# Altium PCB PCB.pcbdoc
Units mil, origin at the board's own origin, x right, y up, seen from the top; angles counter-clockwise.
Board outline 1473.55 x 1860 mil, 2 copper layers (Top Layer, Bottom Layer); 3 components, 4 nets, 11 pads, 0 vias.
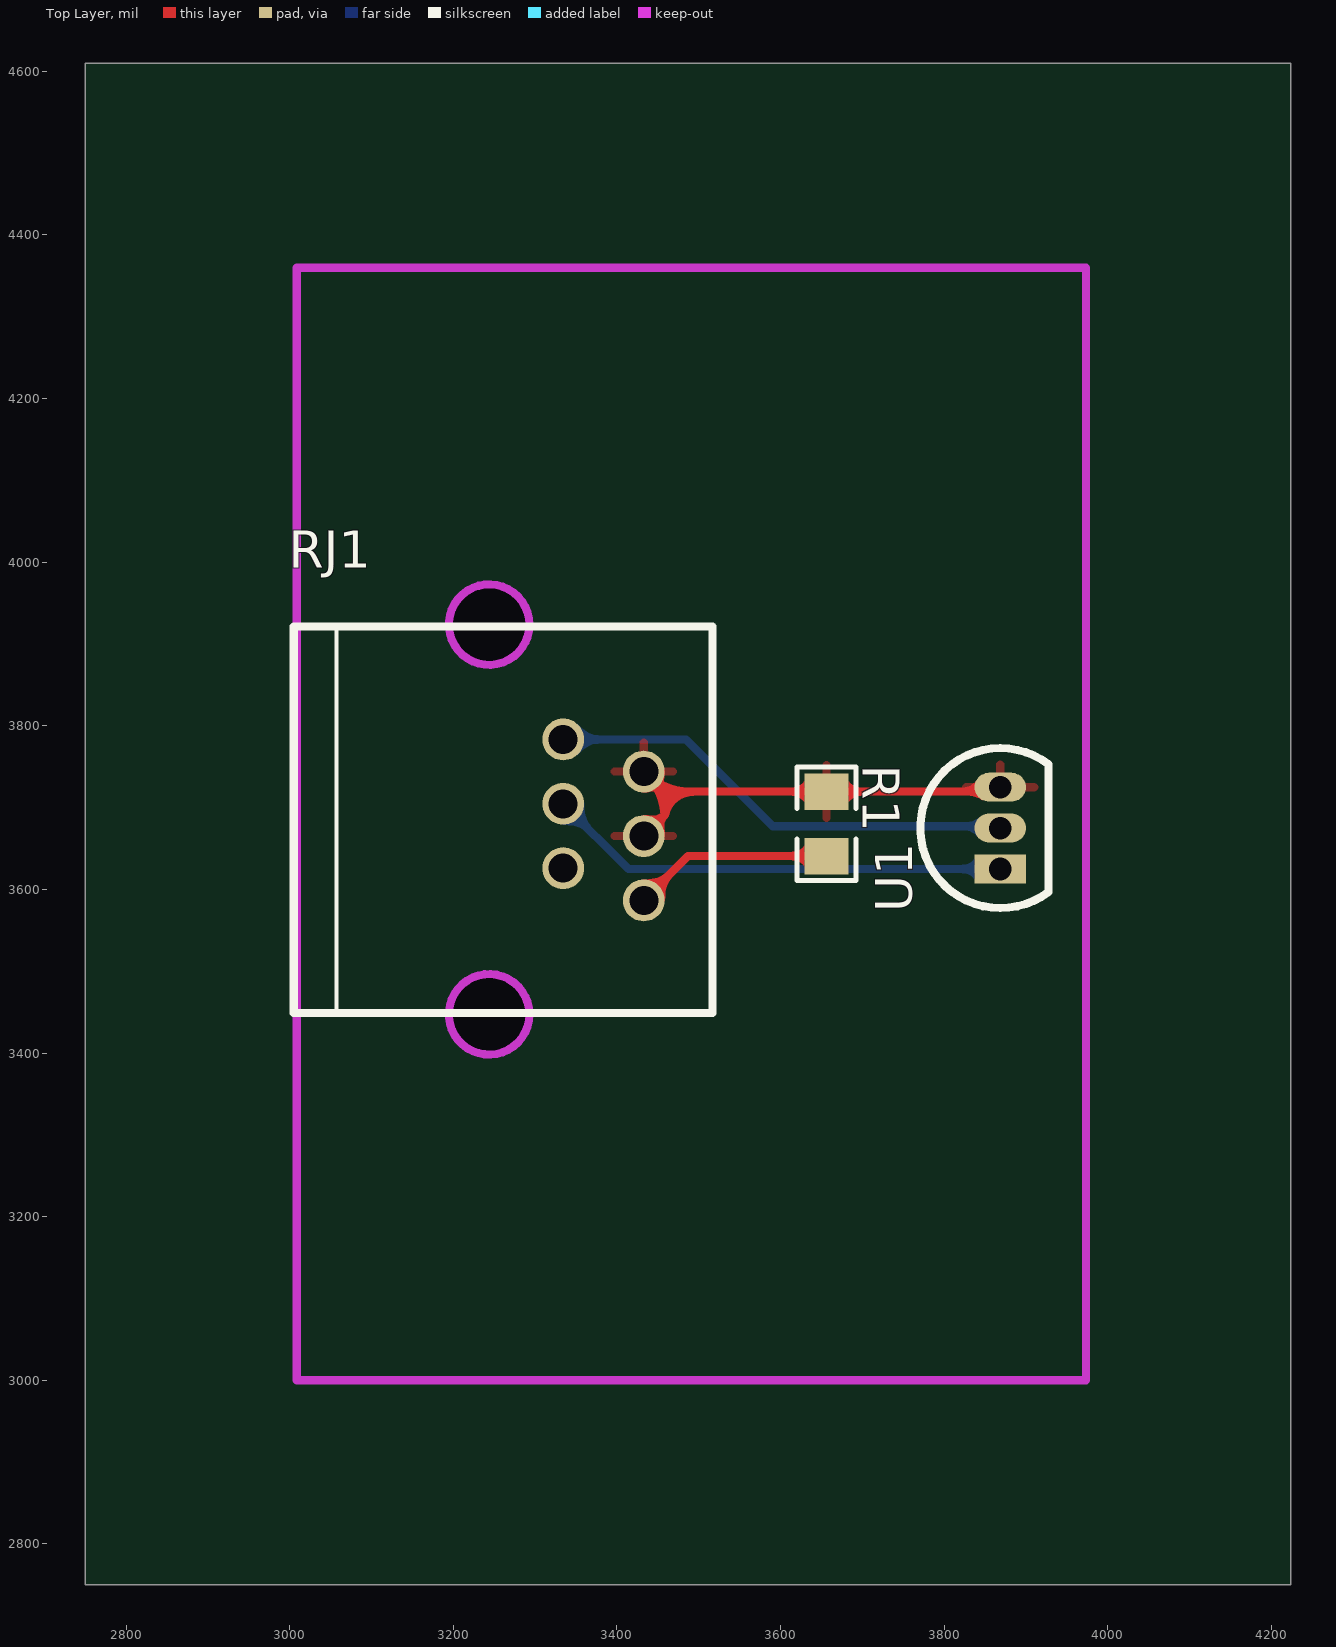
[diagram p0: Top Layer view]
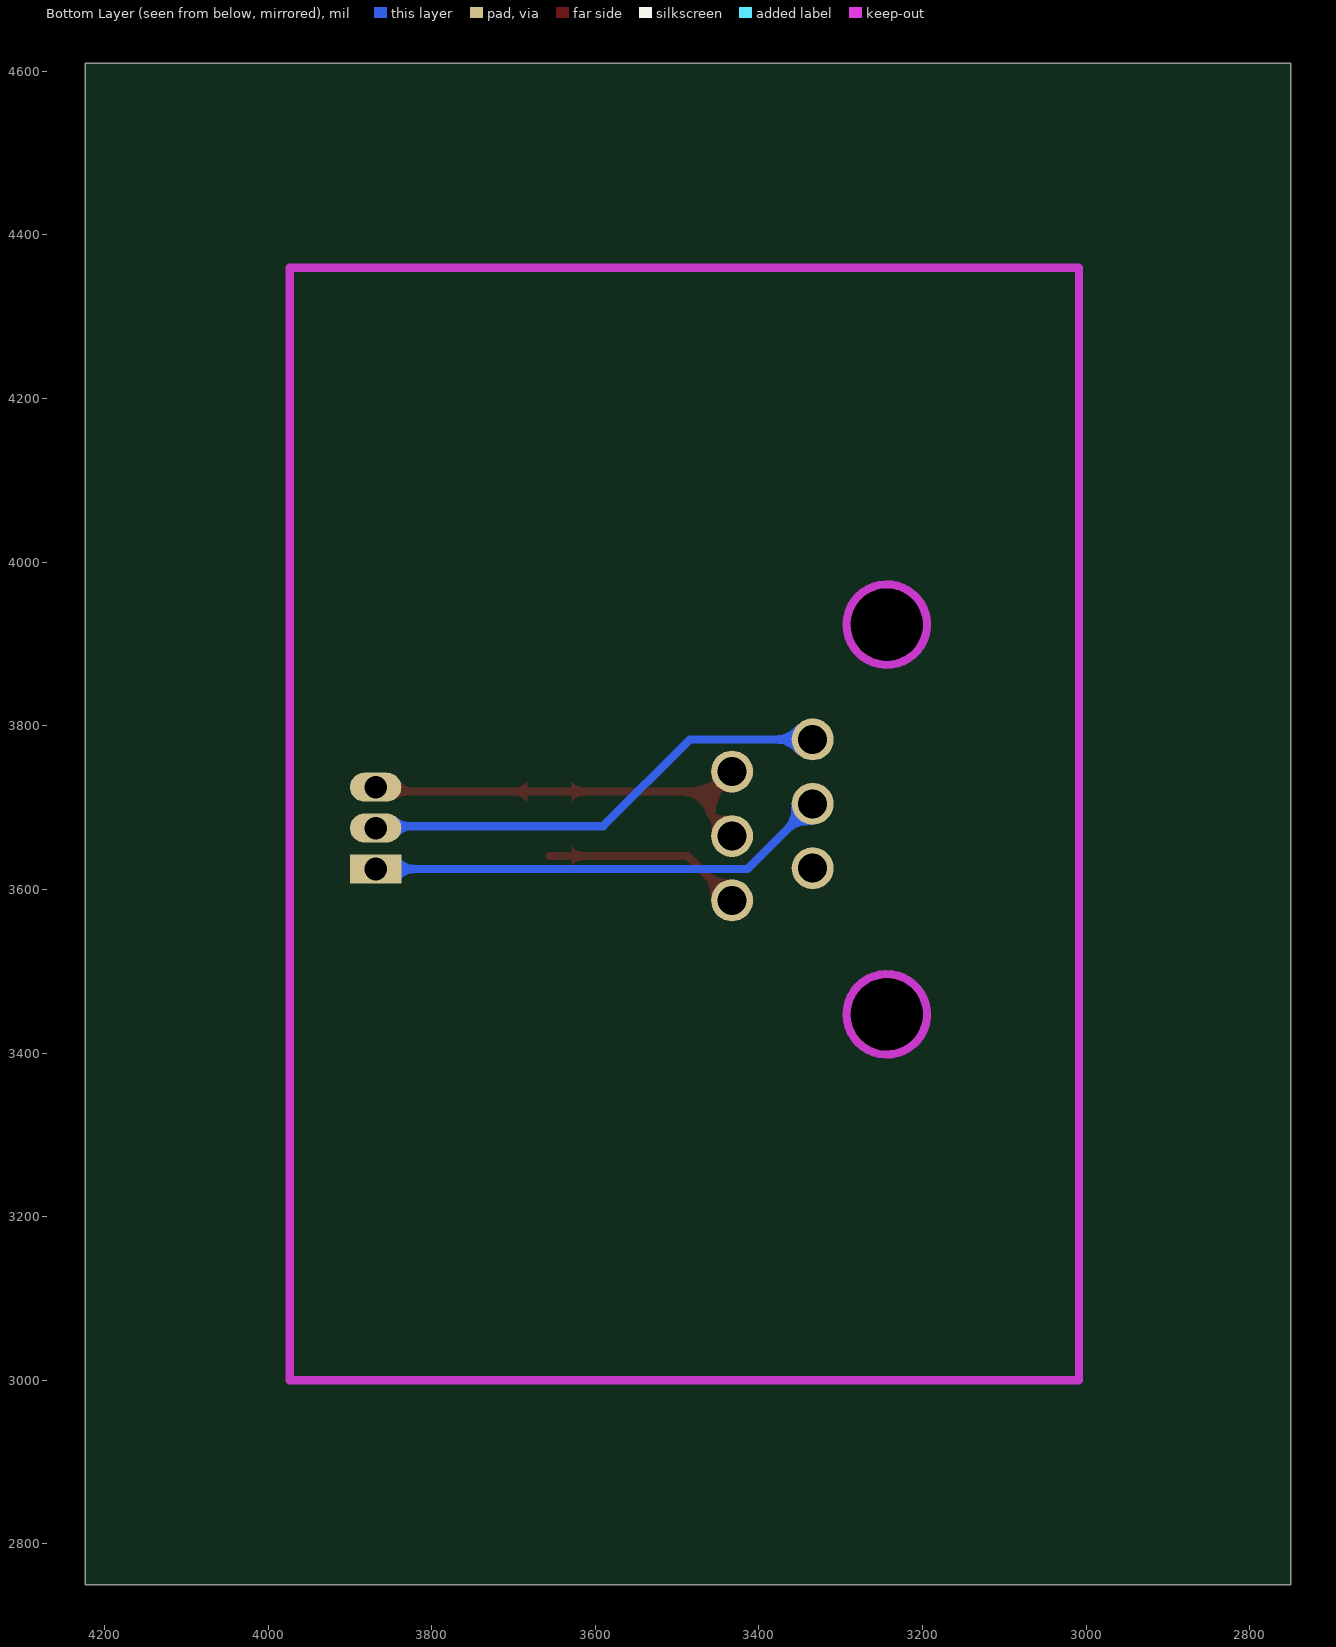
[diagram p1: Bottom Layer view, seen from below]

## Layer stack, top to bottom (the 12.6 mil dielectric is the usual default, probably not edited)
Top Layer: signal copper (thickness not stored)
Dielectric: dielectric 12.6, FR-4, Dk 4.8
Bottom Layer: signal copper (thickness not stored)

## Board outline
4223.55,2750 2750,2750 2750,4610 4223.55,4610

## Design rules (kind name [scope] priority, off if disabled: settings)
Clearance copperThickness1oz [All] p1: gap=7 ignorepadtopadclearanceinfootprint=FALSE except(4: Track-Track; 6: Track-SMDPad SMDPad-SMDPad Track-THPad SMDPad-THPad THPad-THPad Track-Via SMDPad-Via THPad-Via Via-Via SMDPad-Fill THPad-Fill Via-Fill Fill-Fill Track-Region SMDPad-Region THPad-Region Via-Region Region-Region Track-Poly SMDPad-Poly THPad-Poly Via-Poly Fill-Poly Region-Poly Poly-Poly Track-Text SMDPad-Text THPad-Text Via-Text Fill-Text Region-Text Poly-Text Text-Text; 6.9: Track-Hole SMDPad-Hole THPad-Hole Via-Hole Fill-Hole Region-Hole Poly-Hole Text-Hole Sheet-Hole; 11.8: Track-Fill Fill-Region Track-Sheet SMDPad-Sheet THPad-Sheet Via-Sheet Fill-Sheet Region-Sheet Poly-Sheet Text-Sheet)
Clearance copperThickness2oz [All] p1: gap=7 ignorepadtopadclearanceinfootprint=FALSE except(6: Track-SMDPad SMDPad-SMDPad Track-THPad SMDPad-THPad THPad-THPad Track-Via SMDPad-Via THPad-Via Via-Via SMDPad-Fill THPad-Fill Via-Fill Fill-Fill Track-Region SMDPad-Region THPad-Region Via-Region Region-Region Track-Poly SMDPad-Poly THPad-Poly Via-Poly Fill-Poly Region-Poly Poly-Poly Track-Text SMDPad-Text THPad-Text Via-Text Fill-Text Region-Text Poly-Text Text-Text; 6.9: Track-Hole SMDPad-Hole THPad-Hole Via-Hole Fill-Hole Region-Hole Poly-Hole Text-Hole Sheet-Hole; 8: Track-Track; 11.8: Track-Fill Fill-Region Track-Sheet SMDPad-Sheet THPad-Sheet Via-Sheet Fill-Sheet Region-Sheet Poly-Sheet Text-Sheet)
DiffPairsRouting differentialPair [All] p1: maxuncoupledlength=10 maxlimit=6 mostfreqgap=6 toplayer_minwidth=5 toplayer_prefwidth=10 toplayer_maxwidth=100 bottomlayer_minwidth=5 bottomlayer_prefwidth=10 bottomlayer_maxwidth=100
PasteMaskExpansion pasteMaskExpansion [All] p1:
PlaneConnect innerPlane [All] p1: planeconnectstyle=Relief reliefexpansion=20 reliefentries=4 reliefconductorwidth=10 reliefairgap=10
PolygonConnect copperRegion [All] p1: connectstyle=Relief reliefentries=4 reliefconductorwidth=10 polygonreliefangle="90 Angle" airgapwidth=10
RoutingVias viaSize [All] p1: viastyle="Through Hole" holewidth=12.0078 minholewidth=11.811 maxholewidth=248.0314 width=24.0158 minwidth=19.685 maxwidth=393.7008
SolderMaskExpansion solderMaskExpansion [All] p1: useseparateexpansions=TRUE expansion=2 expansionbottom=2
Width copperThickness1oz [All] p1: maxlimit=100 minlimit=5 preferedwidth=10
Width copperThickness2oz [All] p1: maxlimit=100 minlimit=8 preferedwidth=10

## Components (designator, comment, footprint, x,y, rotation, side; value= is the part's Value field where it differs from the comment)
R1 "FRC0805F9100TS" R0805 3656.16,3680.22 r270 top
RJ1 "DS1133-S60BPX" RJ11-TH_DS1133-S60BPX 3383.55,3685 r0 top
U1 "LM35DZ/NOPB" TO-92-3_L4.9-W3.7-P1.27-L 3868.55,3675 r90 top

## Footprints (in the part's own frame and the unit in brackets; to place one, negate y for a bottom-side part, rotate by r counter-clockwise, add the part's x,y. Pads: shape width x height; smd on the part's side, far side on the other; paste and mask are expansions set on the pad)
R0805 [mm]
  rect 1.133x1.377 smd: 1(-1,0) 2(1,0)
  silkscreen extent -1.76,-0.92 1.76,0.92
RJ11-TH_DS1133-S60BPX [mm]
  round 1.3 hole 0.9: 1(1.251,-2.499) 2(-1.251,-1.499) 3(1.251,-0.5) 4(-1.251,0.5) 5(1.251,1.501) 6(-1.251,2.499)
  Multi-Layer board cut-out: -2.302,6.063 -2.473,6.684 -2.93,7.138 -3.552,7.304 -4.174,7.138 -4.631,6.684 -4.802,6.063 -4.802,6.063 -4.631,5.443 -4.174,4.989 -3.552,4.823 -2.93,4.989 -2.473,5.443 -2.302,6.063
  Multi-Layer board cut-out: -2.302,-6.037 -2.473,-5.416 -2.93,-4.962 -3.552,-4.796 -4.174,-4.962 -4.631,-5.416 -4.802,-6.037 -4.802,-6.037 -4.631,-6.657 -4.174,-7.111 -3.552,-7.277 -2.93,-7.111 -2.473,-6.657 -2.302,-6.037
  Multi-Layer keep-out circle w0.254: c-3.552,6.063 r1.25
  Multi-Layer keep-out circle w0.254: c-3.552,-6.037 r1.25
  silkscreen extent -9.62,-6 3.38,6
TO-92-3_L4.9-W3.7-P1.27-L [mm]
  rect 0.9x1.6 hole 0.7: 1(-1.27,0)
  oval 0.9x1.6 hole 0.7: 2(0,0) 3(1.27,0)
  silkscreen extent -2.48,-1.5 2.48,2.48

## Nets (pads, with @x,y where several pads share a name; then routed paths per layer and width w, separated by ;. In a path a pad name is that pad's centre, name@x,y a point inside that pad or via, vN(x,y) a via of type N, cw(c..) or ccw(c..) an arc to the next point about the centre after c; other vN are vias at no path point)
$1N401: 
$1N515: RJ1.4 U1.1 | length 567.3
  Bottom Layer w10: RJ1.4 3414,3625 U1.1
$1N521: RJ1.6 U1.2 | length 579.2
  Bottom Layer w10: RJ1.6 3484.3,3783.4 3590.37,3677.33 3866.22,3677.33 U1.2
GND: R1.1 RJ1.3 RJ1.5 U1.3 | length 513.1
  Top Layer w10: RJ1.3 3458.66,3691.16 3458.66,3719.59 ; RJ1.5 3457.31,3719.59 3458.66,3719.59 ; U1.3 3863.14,3719.59 R1.1 3458.66,3719.59
pads on no net: R1.2 RJ1.1 RJ1.2
copper on no net: | length 245.8
  Top Layer w10: 3432.8,3586.6 3487.05,3640.85 3656.16,3640.85

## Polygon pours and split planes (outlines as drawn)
GND on Top Layer (solid, remove dead copper, pour order 2): 3063.55,3325 3938.55,3325 3938.55,4040 3063.55,4040

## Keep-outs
Board Outline Layer:
  lines w10: 3008.55,3000 3973.55,3000 3973.55,4360 3008.55,4360 3008.55,3000

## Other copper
Top Layer:
  region: 3614.06,3635.85 3614.06,3645.85 ccw(c3614.06,3664.6) 3629.06,3653.35 3629.06,3628.35 ccw(c3614.06,3617.1)
  region net GND: 3614.06,3714.59 3614.06,3724.59 ccw(c3614.06,3743.34) 3629.06,3732.09 3629.06,3707.09 ccw(c3614.06,3695.84)
  region net GND: 3698.27,3724.59 3698.27,3714.59 ccw(c3698.27,3695.84) 3683.27,3707.09 3683.27,3732.09 ccw(c3698.27,3743.34)
  region net GND: 3460.85,3723.12 3453.78,3716.05 3452.41,3717.3 3451.1,3718.28 3449.84,3719 3448.61,3719.51 3447.4,3719.82 3446.19,3719.97 3443.73,3719.88 3438.27,3718.96 3435.06,3718.58 3431.38,3718.55 3458.35,3745.52 3458.32,3741.84 3457.94,3738.63 3457.02,3733.17 3456.93,3730.71 3457.08,3729.5 3457.39,3728.29 3457.9,3727.06 3458.62,3725.8 3459.6,3724.49
  region net GND: 3455.13,3694.7 3462.2,3687.63 3460.93,3686.25 3459.91,3684.9 3459.12,3683.57 3458.53,3682.25 3458.12,3680.93 3457.86,3679.61 3457.7,3676.91 3457.86,3674.05 3458.15,3670.98 3458.38,3667.62 3458.35,3663.88 3431.38,3690.85 3435.12,3690.88 3438.48,3690.65 3441.55,3690.36 3444.41,3690.2 3447.11,3690.36 3448.43,3690.62 3449.75,3691.03 3451.07,3691.62 3452.4,3692.41 3453.75,3693.43
  region: 3459.42,3620.29 3466.49,3613.22 3465.18,3611.79 3464.03,3610.31 3462.16,3607.17 3460.79,3603.85 3459.84,3600.35 3459.22,3596.71 3458.82,3592.96 3458.35,3585.18 3431.38,3612.15 3439.16,3612.62 3442.91,3613.02 3446.55,3613.64 3450.05,3614.59 3453.37,3615.96 3456.51,3617.83 3457.99,3618.98
  region net GND: 3831.64,3714.59 3824,3724.59 3826.07,3724.76 3828.25,3725.24 3830.45,3726.02 3832.59,3727.05 3834.59,3728.3 3836.38,3729.74 3837.87,3731.34 3839,3733.07 3846.64,3709.26 3842.93,3711.22 3839.38,3712.92 3837.57,3713.6 3835.7,3714.13 3833.73,3714.47
  region net GND: 3432.45,3737.38 cw(c3380.74,3685.67) 3453.66,3691.16 3463.66,3691.16 cw(c3493.66,3683.66) 3493.66,3714.59 3489.38,3724.59 cw(c3489.38,3797.01) 3438.17,3745.8
Bottom Layer:
  region net $1N521: 3376.95,3788.4 3376.95,3778.4 3375.01,3778.32 3373.14,3778.08 3369.61,3777.19 3366.29,3775.8 3363.15,3774 3360.13,3771.87 3357.19,3769.49 3351.36,3764.33 3351.36,3802.47 3357.19,3797.31 3360.13,3794.93 3363.15,3792.8 3366.29,3791 3369.61,3789.61 3373.14,3788.72 3375.01,3788.48
  region net $1N515: 3367.99,3678.08 3360.92,3671.01 3359.49,3672.32 3358.01,3673.47 3354.87,3675.34 3351.55,3676.71 3348.05,3677.66 3344.41,3678.28 3340.66,3678.68 3332.88,3679.15 3359.85,3706.12 3360.32,3698.34 3360.72,3694.59 3361.34,3690.95 3362.29,3687.45 3363.66,3684.13 3365.53,3680.99 3366.68,3679.51
  region net $1N521: 3825.68,3672.33 3828.97,3682.33 3831.02,3682.48 3833.02,3682.91 3834.99,3683.57 3836.9,3684.43 3840.56,3686.58 3843.97,3689.05 3840.68,3664.26 3839.36,3665.77 3837.75,3667.23 3835.92,3668.59 3833.93,3669.81 3831.84,3670.84 3829.73,3671.64 3827.65,3672.15
  region net $1N515: 3822.05,3620 3822.05,3630 ccw(c3822.05,3648.75) 3837.05,3637.5 3837.05,3612.5 ccw(c3822.05,3601.25)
